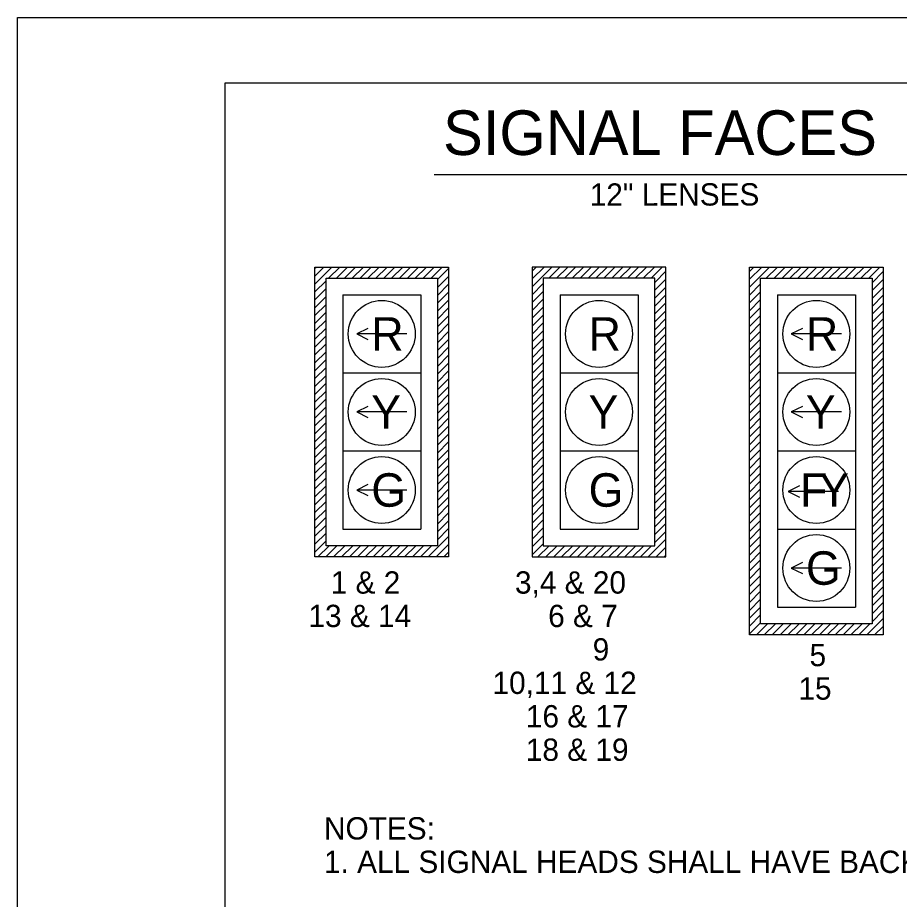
# Model space of a CAD drawing. Extents: x 662183 to 663183, y 642099 to 642739.
# Drawn here: x 662182.6 to 662340.9, y 642581.1 to 642739.3 of the extents above; entities that cross this region are included whole.
import ezdxf

# ---------------------------------------------------------------- set-up
doc = ezdxf.new("R2010")
doc.units = 0
for name, color, linetype in [('Default', 7, 'Continuous'), ('R_Border', 7, 'Continuous'), ('R_No Plot', 7, 'Continuous'), ('T_Drafting', 7, 'Continuous')]:
    doc.layers.add(name, color=color, linetype=linetype)

msp = doc.modelspace()

# ---------------------------------------------------------------- linework, layer by layer
at = {"layer": 'Default'}
msp.add_line((662257.39, 642711.19), (662355.58, 642711.19), dxfattribs=at)
at = {"layer": 'R_Border'}
for p, q in [((662219.86, 642727.62), (663168.4, 642727.62)), ((662219.86, 642111.24), (662219.86, 642727.62))]:
    msp.add_line(p, q, dxfattribs=at)
at = {"layer": 'R_No Plot'}
msp.add_line((662182.66, 642739.3), (663182.66, 642739.3), dxfattribs=at)
msp.add_lwpolyline([(662182.64, 642739.3), (663182.66, 642739.3), (663182.66, 642099.29), (662182.64, 642099.29)], close=True, dxfattribs=at)
at = {"layer": 'T_Drafting'}
for p, q in [((662235.99, 642694.56), (662259.99, 642694.56)), ((662235.99, 642642.56), (662235.99, 642694.56)), ((662235.99, 642691.51), (662239.04, 642694.56)), ((662235.99, 642692.93), (662237.62, 642694.56)), ((662235.99, 642694.34), (662236.21, 642694.56)), ((662238.45, 642692.56), (662240.45, 642694.56)), ((662239.87, 642692.56), (662241.87, 642694.56)), ((662241.28, 642692.56), (662243.28, 642694.56)), ((662242.69, 642692.56), (662244.69, 642694.56)), ((662244.11, 642692.56), (662246.11, 642694.56)), ((662245.52, 642692.56), (662247.52, 642694.56)), ((662246.94, 642692.56), (662248.94, 642694.56)), ((662248.35, 642692.56), (662250.35, 642694.56)), ((662249.76, 642692.56), (662251.76, 642694.56)), ((662251.18, 642692.56), (662253.18, 642694.56)), ((662252.59, 642692.56), (662254.59, 642694.56)), ((662254.01, 642692.56), (662256.01, 642694.56)), ((662255.42, 642692.56), (662257.42, 642694.56)), ((662256.84, 642692.56), (662258.84, 642694.56)), ((662257.99, 642692.3), (662259.99, 642694.3)), ((662259.99, 642694.56), (662259.99, 642642.56)), ((662298.99, 642694.56), (662274.99, 642694.56)), ((662274.99, 642694.56), (662274.99, 642642.56)), ((662274.99, 642691.02), (662278.53, 642694.56)), ((662274.99, 642692.43), (662277.12, 642694.56)), ((662274.99, 642693.84), (662275.71, 642694.56)), ((662277.95, 642692.56), (662279.95, 642694.56)), ((662279.36, 642692.56), (662281.36, 642694.56)), ((662280.78, 642692.56), (662282.78, 642694.56)), ((662282.19, 642692.56), (662284.19, 642694.56)), ((662283.6, 642692.56), (662285.6, 642694.56)), ((662285.02, 642692.56), (662287.02, 642694.56)), ((662286.43, 642692.56), (662288.43, 642694.56)), ((662287.85, 642692.56), (662289.85, 642694.56)), ((662289.26, 642692.56), (662291.26, 642694.56)), ((662290.68, 642692.56), (662292.68, 642694.56)), ((662292.09, 642692.56), (662294.09, 642694.56)), ((662293.5, 642692.56), (662295.5, 642694.56)), ((662294.92, 642692.56), (662296.92, 642694.56)), ((662296.33, 642692.56), (662298.33, 642694.56)), ((662298.99, 642642.56), (662298.99, 642694.56)), ((662313.99, 642628.56), (662313.99, 642694.56)), ((662313.99, 642694.56), (662337.99, 642694.56)), ((662313.99, 642690.96), (662317.59, 642694.56)), ((662313.99, 642692.37), (662316.18, 642694.56)), ((662313.99, 642693.78), (662314.77, 642694.56)), ((662317.01, 642692.56), (662319.01, 642694.56)), ((662318.42, 642692.56), (662320.42, 642694.56)), ((662319.84, 642692.56), (662321.84, 642694.56)), ((662321.25, 642692.56), (662323.25, 642694.56)), ((662322.66, 642692.56), (662324.66, 642694.56)), ((662324.08, 642692.56), (662326.08, 642694.56)), ((662325.49, 642692.56), (662327.49, 642694.56)), ((662326.91, 642692.56), (662328.91, 642694.56)), ((662328.32, 642692.56), (662330.32, 642694.56)), ((662329.74, 642692.56), (662331.74, 642694.56)), ((662331.15, 642692.56), (662333.15, 642694.56)), ((662332.56, 642692.56), (662334.56, 642694.56)), ((662333.98, 642692.56), (662335.98, 642694.56)), ((662335.39, 642692.56), (662337.39, 642694.56)), ((662337.99, 642694.56), (662337.99, 642628.56)), ((662257.99, 642690.89), (662259.99, 642692.89)), ((662296.99, 642691.8), (662298.99, 642693.8)), ((662296.99, 642690.39), (662298.99, 642692.39)), ((662335.99, 642691.74), (662337.99, 642693.74)), ((662335.99, 642690.33), (662337.99, 642692.33)), ((662235.99, 642690.1), (662237.99, 642692.1)), ((662235.99, 642688.68), (662237.99, 642690.68)), ((662257.99, 642689.47), (662259.99, 642691.47)), ((662274.99, 642689.6), (662276.99, 642691.6)), ((662296.99, 642688.97), (662298.99, 642690.97)), ((662313.99, 642689.54), (662315.99, 642691.54)), ((662335.99, 642688.91), (662337.99, 642690.91)), ((662235.99, 642687.27), (662237.99, 642689.27)), ((662240.99, 642689.56), (662254.99, 642689.56)), ((662240.99, 642689.56), (662240.99, 642675.56)), ((662254.99, 642689.56), (662254.99, 642675.56)), ((662257.99, 642688.06), (662259.99, 642690.06)), ((662274.99, 642688.19), (662276.99, 642690.19)), ((662279.99, 642689.56), (662293.99, 642689.56)), ((662279.99, 642689.56), (662279.99, 642675.56)), ((662293.99, 642689.56), (662293.99, 642675.56)), ((662296.99, 642687.56), (662298.99, 642689.56)), ((662313.99, 642688.13), (662315.99, 642690.13)), ((662318.99, 642689.56), (662332.99, 642689.56)), ((662318.99, 642689.56), (662318.99, 642675.56)), ((662332.99, 642689.56), (662332.99, 642675.56)), ((662335.99, 642687.5), (662337.99, 642689.5)), ((662235.99, 642685.86), (662237.99, 642687.86)), ((662257.99, 642686.64), (662259.99, 642688.64)), ((662274.99, 642686.77), (662276.99, 642688.77)), ((662296.99, 642686.15), (662298.99, 642688.15)), ((662313.99, 642686.71), (662315.99, 642688.71)), ((662335.99, 642686.09), (662337.99, 642688.09)), ((662235.99, 642684.44), (662237.99, 642686.44)), ((662257.99, 642685.23), (662259.99, 642687.23)), ((662274.99, 642685.36), (662276.99, 642687.36)), ((662274.99, 642683.94), (662276.99, 642685.94)), ((662296.99, 642684.73), (662298.99, 642686.73)), ((662313.99, 642685.3), (662315.99, 642687.3)), ((662335.99, 642684.67), (662337.99, 642686.67)), ((662235.99, 642683.03), (662237.99, 642685.03)), ((662257.99, 642683.81), (662259.99, 642685.81)), ((662257.99, 642682.4), (662259.99, 642684.4)), ((662274.99, 642682.53), (662276.99, 642684.53)), ((662296.99, 642683.32), (662298.99, 642685.32)), ((662313.99, 642683.88), (662315.99, 642685.88)), ((662313.99, 642682.47), (662315.99, 642684.47)), ((662335.99, 642683.26), (662337.99, 642685.26)), ((662235.99, 642681.61), (662237.99, 642683.61)), ((662257.99, 642680.99), (662259.99, 642682.99)), ((662274.99, 642681.12), (662276.99, 642683.12)), ((662296.99, 642681.9), (662298.99, 642683.9)), ((662313.99, 642681.06), (662315.99, 642683.06)), ((662335.99, 642681.84), (662337.99, 642683.84)), ((662235.99, 642680.2), (662237.99, 642682.2)), ((662252.49, 642682.56), (662243.49, 642682.56)), ((662257.99, 642679.57), (662259.99, 642681.57)), ((662274.99, 642679.7), (662276.99, 642681.7)), ((662296.99, 642680.49), (662298.99, 642682.49)), ((662313.99, 642679.64), (662315.99, 642681.64)), ((662330.49, 642682.56), (662321.49, 642682.56)), ((662335.99, 642680.43), (662337.99, 642682.43)), ((662235.99, 642678.78), (662237.99, 642680.78)), ((662257.99, 642678.16), (662259.99, 642680.16)), ((662274.99, 642678.29), (662276.99, 642680.29)), ((662296.99, 642679.07), (662298.99, 642681.07)), ((662296.99, 642677.66), (662298.99, 642679.66)), ((662313.99, 642678.23), (662315.99, 642680.23)), ((662335.99, 642679.01), (662337.99, 642681.01)), ((662335.99, 642677.6), (662337.99, 642679.6)), ((662235.99, 642677.37), (662237.99, 642679.37)), ((662257.99, 642676.74), (662259.99, 642678.74)), ((662274.99, 642676.87), (662276.99, 642678.87)), ((662296.99, 642676.25), (662298.99, 642678.25)), ((662313.99, 642676.81), (662315.99, 642678.81)), ((662335.99, 642676.19), (662337.99, 642678.19)), ((662235.99, 642675.96), (662237.99, 642677.96)), ((662235.99, 642674.54), (662237.99, 642676.54)), ((662257.99, 642675.33), (662259.99, 642677.33)), ((662274.99, 642675.46), (662276.99, 642677.46)), ((662296.99, 642674.83), (662298.99, 642676.83)), ((662313.99, 642675.4), (662315.99, 642677.4)), ((662335.99, 642674.77), (662337.99, 642676.77)), ((662235.99, 642673.13), (662237.99, 642675.13)), ((662240.99, 642675.56), (662254.99, 642675.56)), ((662240.99, 642675.56), (662240.99, 642661.56)), ((662254.99, 642675.56), (662254.99, 642661.56)), ((662257.99, 642673.91), (662259.99, 642675.91)), ((662274.99, 642674.05), (662276.99, 642676.05)), ((662279.99, 642675.56), (662293.99, 642675.56)), ((662279.99, 642675.56), (662279.99, 642661.56)), ((662293.99, 642675.56), (662293.99, 642661.56)), ((662296.99, 642673.42), (662298.99, 642675.42)), ((662313.99, 642673.98), (662315.99, 642675.98)), ((662318.99, 642675.56), (662332.99, 642675.56)), ((662318.99, 642675.56), (662318.99, 642661.56)), ((662332.99, 642675.56), (662332.99, 642661.56)), ((662335.99, 642673.36), (662337.99, 642675.36)), ((662235.99, 642671.71), (662237.99, 642673.71)), ((662257.99, 642672.5), (662259.99, 642674.5)), ((662274.99, 642672.63), (662276.99, 642674.63)), ((662296.99, 642672), (662298.99, 642674)), ((662313.99, 642672.57), (662315.99, 642674.57)), ((662335.99, 642671.94), (662337.99, 642673.94)), ((662235.99, 642670.3), (662237.99, 642672.3)), ((662257.99, 642671.09), (662259.99, 642673.09)), ((662257.99, 642669.67), (662259.99, 642671.67)), ((662274.99, 642671.22), (662276.99, 642673.22)), ((662274.99, 642669.8), (662276.99, 642671.8)), ((662296.99, 642670.59), (662298.99, 642672.59)), ((662313.99, 642671.16), (662315.99, 642673.16)), ((662313.99, 642669.74), (662315.99, 642671.74)), ((662335.99, 642670.53), (662337.99, 642672.53)), ((662235.99, 642668.89), (662237.99, 642670.89)), ((662257.99, 642668.26), (662259.99, 642670.26)), ((662274.99, 642668.39), (662276.99, 642670.39)), ((662296.99, 642669.18), (662298.99, 642671.18)), ((662313.99, 642668.33), (662315.99, 642670.33)), ((662335.99, 642669.11), (662337.99, 642671.11)), ((662235.99, 642667.47), (662237.99, 642669.47)), ((662252.49, 642668.56), (662243.49, 642668.56)), ((662257.99, 642666.84), (662259.99, 642668.84)), ((662274.99, 642666.97), (662276.99, 642668.97)), ((662296.99, 642667.76), (662298.99, 642669.76)), ((662313.99, 642666.91), (662315.99, 642668.91)), ((662330.49, 642668.56), (662321.49, 642668.56)), ((662335.99, 642667.7), (662337.99, 642669.7)), ((662235.99, 642666.06), (662237.99, 642668.06)), ((662257.99, 642665.43), (662259.99, 642667.43)), ((662274.99, 642665.56), (662276.99, 642667.56)), ((662296.99, 642666.35), (662298.99, 642668.35)), ((662296.99, 642664.93), (662298.99, 642666.93)), ((662313.99, 642665.5), (662315.99, 642667.5)), ((662335.99, 642666.29), (662337.99, 642668.29)), ((662235.99, 642664.64), (662237.99, 642666.64)), ((662257.99, 642664.02), (662259.99, 642666.02)), ((662274.99, 642664.15), (662276.99, 642666.15)), ((662296.99, 642663.52), (662298.99, 642665.52)), ((662313.99, 642664.09), (662315.99, 642666.09)), ((662335.99, 642664.87), (662337.99, 642666.87)), ((662335.99, 642663.46), (662337.99, 642665.46)), ((662235.99, 642663.23), (662237.99, 642665.23)), ((662235.99, 642661.81), (662237.99, 642663.81)), ((662257.99, 642662.6), (662259.99, 642664.6)), ((662274.99, 642662.73), (662276.99, 642664.73)), ((662296.99, 642662.1), (662298.99, 642664.1)), ((662313.99, 642662.67), (662315.99, 642664.67)), ((662335.99, 642662.04), (662337.99, 642664.04)), ((662235.99, 642660.4), (662237.99, 642662.4)), ((662257.99, 642661.19), (662259.99, 642663.19)), ((662274.99, 642661.32), (662276.99, 642663.32)), ((662296.99, 642660.69), (662298.99, 642662.69)), ((662313.99, 642661.26), (662315.99, 642663.26)), ((662335.99, 642660.63), (662337.99, 642662.63)), ((662235.99, 642658.99), (662237.99, 642660.99)), ((662240.99, 642661.56), (662254.99, 642661.56)), ((662240.99, 642661.56), (662240.99, 642647.56)), ((662254.99, 642661.56), (662254.99, 642647.56)), ((662257.99, 642659.77), (662259.99, 642661.77)), ((662274.99, 642659.9), (662276.99, 642661.9)), ((662279.99, 642661.56), (662293.99, 642661.56)), ((662279.99, 642661.56), (662279.99, 642647.56)), ((662293.99, 642661.56), (662293.99, 642647.56)), ((662296.99, 642659.28), (662298.99, 642661.28)), ((662313.99, 642659.84), (662315.99, 642661.84)), ((662318.99, 642661.56), (662332.99, 642661.56)), ((662318.99, 642661.56), (662318.99, 642647.56)), ((662332.99, 642661.56), (662332.99, 642647.56)), ((662335.99, 642659.22), (662337.99, 642661.22)), ((662235.99, 642657.57), (662237.99, 642659.57)), ((662257.99, 642658.36), (662259.99, 642660.36)), ((662274.99, 642658.49), (662276.99, 642660.49)), ((662274.99, 642657.07), (662276.99, 642659.07)), ((662296.99, 642657.86), (662298.99, 642659.86)), ((662313.99, 642658.43), (662315.99, 642660.43)), ((662313.99, 642657.01), (662315.99, 642659.01)), ((662335.99, 642657.8), (662337.99, 642659.8)), ((662235.99, 642656.16), (662237.99, 642658.16)), ((662257.99, 642656.94), (662259.99, 642658.94)), ((662257.99, 642655.53), (662259.99, 642657.53)), ((662274.99, 642655.66), (662276.99, 642657.66)), ((662296.99, 642656.45), (662298.99, 642658.45)), ((662313.99, 642655.6), (662315.99, 642657.6)), ((662335.99, 642656.39), (662337.99, 642658.39)), ((662235.99, 642654.74), (662237.99, 642656.74)), ((662257.99, 642654.12), (662259.99, 642656.12)), ((662274.99, 642654.25), (662276.99, 642656.25)), ((662296.99, 642655.03), (662298.99, 642657.03)), ((662313.99, 642654.19), (662315.99, 642656.19)), ((662335.99, 642654.97), (662337.99, 642656.97)), ((662235.99, 642653.33), (662237.99, 642655.33)), ((662252.49, 642654.56), (662243.49, 642654.56)), ((662257.99, 642652.7), (662259.99, 642654.7)), ((662274.99, 642652.83), (662276.99, 642654.83)), ((662296.99, 642653.62), (662298.99, 642655.62)), ((662313.99, 642652.77), (662315.99, 642654.77)), ((662329.96, 642654.29), (662320.96, 642654.29)), ((662335.99, 642653.56), (662337.99, 642655.56)), ((662235.99, 642651.91), (662237.99, 642653.91)), ((662257.99, 642651.29), (662259.99, 642653.29)), ((662274.99, 642651.42), (662276.99, 642653.42)), ((662296.99, 642652.2), (662298.99, 642654.2)), ((662296.99, 642650.79), (662298.99, 642652.79)), ((662313.99, 642651.36), (662315.99, 642653.36)), ((662335.99, 642652.14), (662337.99, 642654.14)), ((662335.99, 642650.73), (662337.99, 642652.73)), ((662235.99, 642650.5), (662237.99, 642652.5)), ((662257.99, 642649.87), (662259.99, 642651.87)), ((662274.99, 642650), (662276.99, 642652)), ((662296.99, 642649.38), (662298.99, 642651.38)), ((662313.99, 642649.94), (662315.99, 642651.94)), ((662335.99, 642649.32), (662337.99, 642651.32)), ((662235.99, 642649.09), (662237.99, 642651.09)), ((662235.99, 642647.67), (662237.99, 642649.67)), ((662257.99, 642648.46), (662259.99, 642650.46)), ((662274.99, 642648.59), (662276.99, 642650.59)), ((662296.99, 642647.96), (662298.99, 642649.96)), ((662313.99, 642648.53), (662315.99, 642650.53)), ((662335.99, 642647.9), (662337.99, 642649.9)), ((662235.99, 642646.26), (662237.99, 642648.26)), ((662257.99, 642647.04), (662259.99, 642649.04)), ((662274.99, 642647.18), (662276.99, 642649.18)), ((662296.99, 642646.55), (662298.99, 642648.55)), ((662313.99, 642647.11), (662315.99, 642649.11)), ((662335.99, 642646.49), (662337.99, 642648.49)), ((662235.99, 642644.84), (662237.99, 642646.84)), ((662240.99, 642647.56), (662254.99, 642647.56)), ((662257.99, 642645.63), (662259.99, 642647.63)), ((662274.99, 642645.76), (662276.99, 642647.76)), ((662274.99, 642644.35), (662276.99, 642646.35)), ((662279.99, 642647.56), (662293.99, 642647.56)), ((662296.99, 642645.13), (662298.99, 642647.13)), ((662313.99, 642645.7), (662315.99, 642647.7)), ((662318.99, 642647.56), (662332.99, 642647.56)), ((662318.99, 642647.56), (662318.99, 642633.56)), ((662332.99, 642647.56), (662332.99, 642633.56)), ((662335.99, 642645.07), (662337.99, 642647.07)), ((662235.99, 642643.43), (662237.99, 642645.43)), ((662256.33, 642642.56), (662259.99, 642646.22)), ((662257.75, 642642.56), (662259.99, 642644.8)), ((662274.99, 642642.93), (662276.99, 642644.93)), ((662295.83, 642642.56), (662298.99, 642645.72)), ((662313.99, 642644.29), (662315.99, 642646.29)), ((662313.99, 642642.87), (662315.99, 642644.87)), ((662335.99, 642643.66), (662337.99, 642645.66)), ((662236.53, 642642.56), (662238.53, 642644.56)), ((662237.95, 642642.56), (662239.95, 642644.56)), ((662239.36, 642642.56), (662241.36, 642644.56)), ((662240.78, 642642.56), (662242.78, 642644.56)), ((662242.19, 642642.56), (662244.19, 642644.56)), ((662243.61, 642642.56), (662245.61, 642644.56)), ((662245.02, 642642.56), (662247.02, 642644.56)), ((662246.43, 642642.56), (662248.43, 642644.56)), ((662247.85, 642642.56), (662249.85, 642644.56)), ((662249.26, 642642.56), (662251.26, 642644.56)), ((662250.68, 642642.56), (662252.68, 642644.56)), ((662252.09, 642642.56), (662254.09, 642644.56)), ((662253.5, 642642.56), (662255.5, 642644.56)), ((662254.92, 642642.56), (662256.92, 642644.56)), ((662259.16, 642642.56), (662259.99, 642643.39)), ((662276.03, 642642.56), (662278.03, 642644.56)), ((662277.45, 642642.56), (662279.45, 642644.56)), ((662278.86, 642642.56), (662280.86, 642644.56)), ((662280.27, 642642.56), (662282.27, 642644.56)), ((662281.69, 642642.56), (662283.69, 642644.56)), ((662283.1, 642642.56), (662285.1, 642644.56)), ((662284.52, 642642.56), (662286.52, 642644.56)), ((662285.93, 642642.56), (662287.93, 642644.56)), ((662287.34, 642642.56), (662289.34, 642644.56)), ((662288.76, 642642.56), (662290.76, 642644.56)), ((662290.17, 642642.56), (662292.17, 642644.56)), ((662291.59, 642642.56), (662293.59, 642644.56)), ((662293, 642642.56), (662295, 642644.56)), ((662294.42, 642642.56), (662296.42, 642644.56)), ((662297.24, 642642.56), (662298.99, 642644.31)), ((662313.99, 642641.46), (662315.99, 642643.46)), ((662335.99, 642642.24), (662337.99, 642644.24)), ((662259.99, 642642.56), (662235.99, 642642.56)), ((662274.99, 642642.56), (662298.99, 642642.56)), ((662298.66, 642642.56), (662298.99, 642642.89)), ((662313.99, 642640.04), (662315.99, 642642.04)), ((662335.99, 642640.83), (662337.99, 642642.83)), ((662313.99, 642638.63), (662315.99, 642640.63)), ((662330.49, 642640.56), (662321.49, 642640.56)), ((662335.99, 642639.42), (662337.99, 642641.42)), ((662313.99, 642637.22), (662315.99, 642639.22)), ((662335.99, 642638), (662337.99, 642640)), ((662335.99, 642636.59), (662337.99, 642638.59)), ((662313.99, 642635.8), (662315.99, 642637.8)), ((662335.99, 642635.17), (662337.99, 642637.17)), ((662313.99, 642634.39), (662315.99, 642636.39)), ((662335.99, 642633.76), (662337.99, 642635.76)), ((662313.99, 642632.97), (662315.99, 642634.97)), ((662335.99, 642632.35), (662337.99, 642634.35)), ((662313.99, 642631.56), (662315.99, 642633.56)), ((662313.99, 642630.14), (662315.99, 642632.14)), ((662318.99, 642633.56), (662332.99, 642633.56)), ((662335.99, 642630.93), (662337.99, 642632.93)), ((662313.99, 642628.73), (662315.99, 642630.73)), ((662315.23, 642628.56), (662317.23, 642630.56)), ((662316.65, 642628.56), (662318.65, 642630.56)), ((662318.06, 642628.56), (662320.06, 642630.56)), ((662319.48, 642628.56), (662321.48, 642630.56)), ((662320.89, 642628.56), (662322.89, 642630.56)), ((662322.3, 642628.56), (662324.3, 642630.56)), ((662323.72, 642628.56), (662325.72, 642630.56)), ((662325.13, 642628.56), (662327.13, 642630.56)), ((662326.55, 642628.56), (662328.55, 642630.56)), ((662327.96, 642628.56), (662329.96, 642630.56)), ((662329.38, 642628.56), (662331.38, 642630.56)), ((662330.79, 642628.56), (662332.79, 642630.56)), ((662332.2, 642628.56), (662334.2, 642630.56)), ((662333.62, 642628.56), (662335.62, 642630.56)), ((662335.03, 642628.56), (662337.99, 642631.52)), ((662336.45, 642628.56), (662337.99, 642630.1)), ((662337.99, 642628.56), (662313.99, 642628.56)), ((662337.86, 642628.56), (662337.99, 642628.69))]:
    msp.add_line(p, q, dxfattribs=at)
for points in [[(662237.99, 642692.56), (662257.99, 642692.56), (662257.99, 642644.56), (662237.99, 642644.56)], [(662296.99, 642644.56), (662296.99, 642692.56), (662276.99, 642692.56), (662276.99, 642644.56)], [(662315.99, 642630.56), (662315.99, 642692.56), (662335.99, 642692.56), (662335.99, 642630.56)]]:
    msp.add_lwpolyline(points, close=True, dxfattribs=at)
for points in [[(662245.49, 642683.56), (662243.49, 642682.56), (662245.49, 642681.56)], [(662323.49, 642683.56), (662321.49, 642682.56), (662323.49, 642681.56)], [(662245.49, 642669.56), (662243.49, 642668.56), (662245.49, 642667.56)], [(662323.49, 642669.56), (662321.49, 642668.56), (662323.49, 642667.56)], [(662245.49, 642655.56), (662243.49, 642654.56), (662245.49, 642653.56)], [(662322.96, 642655.29), (662320.96, 642654.29), (662322.96, 642653.29)], [(662323.49, 642641.56), (662321.49, 642640.56), (662323.49, 642639.56)]]:
    msp.add_lwpolyline(points, dxfattribs=at)
for centre in [(662247.99, 642682.56), (662286.99, 642682.56), (662325.99, 642682.56), (662247.99, 642668.56), (662286.99, 642668.56), (662325.99, 642668.56), (662247.99, 642654.56), (662286.99, 642654.56), (662325.99, 642654.56), (662325.99, 642640.56)]:
    msp.add_circle(centre, 6, dxfattribs=at)

# ---------------------------------------------------------------- texts
at = {"layer": 'Default'}
for s, height, p in [('SIGNAL FACES', 8, (662258.99, 642714.66)), ('1 & 2', 4, (662238.83, 642635.97)), ('3,4 & 20', 4, (662271.9, 642635.97)), ('13 & 14', 4, (662234.83, 642629.97)), ('6 & 7', 4, (662277.86, 642629.97)), ('9', 4, (662285.85, 642623.97)), ('5', 4, (662324.77, 642622.95)), ('10,11 & 12', 4, (662267.87, 642617.97)), ('15', 4, (662322.77, 642616.95)), ('16 & 17', 4, (662273.86, 642611.97)), ('18 & 19', 4, (662273.85, 642605.97)), ('NOTES:', 4, (662237.62, 642591.86)), ('1. ALL SIGNAL HEADS SHALL HAVE BACKPLATES.', 4, (662237.62, 642585.86))]:
    msp.add_text(s, height=height, dxfattribs=at).set_placement(p)
at = {"layer": 'T_Drafting'}
msp.add_text('12" LENSES', height=4, rotation=0.072, dxfattribs=at).set_placement((662285.32, 642705.56))
for s, p in [('R', (662246.12, 642679.56)), ('R', (662285.12, 642679.56)), ('R', (662324.12, 642679.56)), ('Y', (662246.1, 642665.56)), ('Y', (662285.1, 642665.56)), ('Y', (662324.1, 642665.56)), ('G', (662246.12, 642651.56)), ('G', (662285.12, 642651.56)), ('F', (662323.08, 642651.56)), ('Y', (662326.51, 642651.56)), ('G', (662324.12, 642637.56))]:
    msp.add_text(s, height=6, dxfattribs=at).set_placement(p)

doc.saveas('drawing.dxf')
